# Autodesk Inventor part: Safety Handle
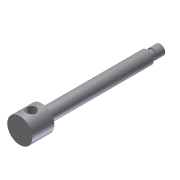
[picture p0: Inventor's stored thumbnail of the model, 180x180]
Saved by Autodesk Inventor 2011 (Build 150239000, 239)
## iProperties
Shininess: 77.0
Length Units: 11269
Angle Units: 11279
Time Units: 11290
Mass Units: 11283
Length Display Precision: 3
Angle Display Precision: 2
Created: 2002-02
Part Number: Safety Handle
Document SubType Name: Modeling
Designer: ***
Density: 1 g/cm^3
Density: 0.0
Volumn: 0.0
Area: 0.0
PropertySet Name: Model Information
Control State: 0
Master: False
Checked Out: False
Author: ***
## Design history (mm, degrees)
sketch "Sketch1"
  geometry: L1 (0, 140)-(5, 140); L2 (5, 140)-(5, 132); L3 (5, 132)-(4, 132); L4 (4, 132)-(4, 127); L5 (4, 127)-(6.5, 127); L6 (6.5, 127)-(6.5, 25); L7 (6.5, 25)-(4, 25); L8 (4, 25)-(4, 22); L9 (4, 22)-(12.5, 22); L10 (12.5, 22)-(12.5, 0); L11 (12.5, 0)-(0, 0); L12 (0, 0)-(0, 140)
  constraints: 24 end point, 10 parallel, 1 horizontal, 1 perpendicular
  dimensions: "d0" = 10 diameter of L2 L12; "d1" = 8 diameter of L4 L12; "d2" = 13 diameter of L6 L12; "d3" = 8 diameter of L7.end L12; "d4" = 25 diameter of L10 L12; "d5" = 3 distance from line of L7.end L9; "d6" = 8 distance of L1.end L2.end; "d7" = 13 vertical distance of L1.end L5.end; "d8" = 22 distance of L9.end L10.end; "d10" = 102 distance of L5.end L6.end
revolve "Revolution1" sketch "Sketch1" stored, may be unused: angle "d11" = 90 deg
sketch "Sketch3"
  geometry: L1 (-12.5, 0)-(12.5, 0) reference; C1 r 5 at (-0.113, 11)
  constraints: 1 centre point
  dimensions: "d13" = 10 diameter of C1; "d14" = 11 distance from line of L1 C1.centre
extrude "Extrusion1" cut sketch "Sketch3" stored distance "d15" = 10; taper "d16" = 0 deg
body "Solid1"
